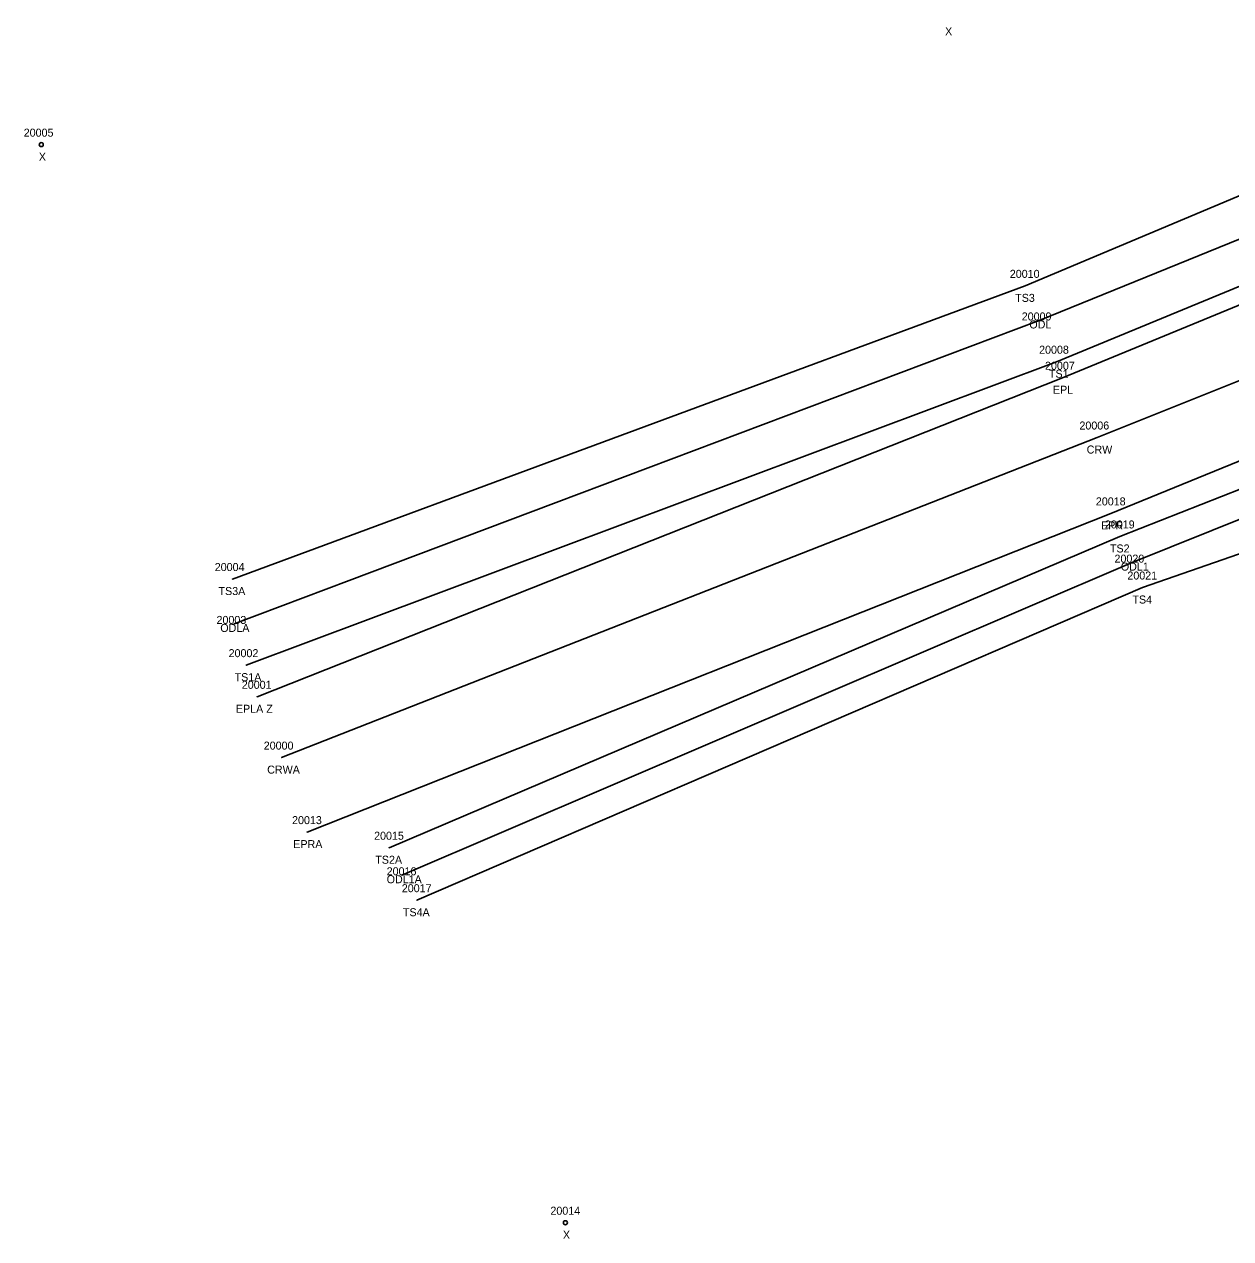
# Model space of a CAD drawing. Extents: x 1966740 to 1969291, y 1117378 to 1118461.
# Drawn here: x 1966740.4 to 1966891.2, y 1117389.8 to 1117541.5 of the extents above; entities that cross this region are included whole.
import ezdxf

# ---------------------------------------------------------------- set-up
doc = ezdxf.new("R2010")
doc.units = 0
for name, color, linetype in [('RD_DTM_BkLn1', 7, 'Continuous'), ('RD_DTM_BkLn2', 7, 'Continuous'), ('RD_EX_H2O', 7, 'Continuous'), ('RD_EX_H2O_txCode', 7, 'Continuous'), ('RD_EX_Road', 7, 'Continuous'), ('RD_EX_Road_txCode', 7, 'Continuous'), ('RD_SMD_Locator', 7, 'Continuous'), ('RD_SMD_Misc', 7, 'Continuous')]:
    doc.layers.add(name, color=color, linetype=linetype)

msp = doc.modelspace()

# ---------------------------------------------------------------- linework, layer by layer
at = {"layer": 'RD_DTM_BkLn1'}
msp.add_lwpolyline([(1966772.57, 1117449.88), (1966874.49, 1117489.87), (1966974.64, 1117529.93), (1967075.06, 1117571.68), (1967175.91, 1117613.34), (1967274.11, 1117653.69), (1967325.25, 1117674.8), (1967374.73, 1117695), (1967473.9, 1117733.1), (1967569.8, 1117771.9), (1967665.19, 1117809.79), (1967697.89, 1117822.8)], dxfattribs=at)
at = {"layer": 'RD_DTM_BkLn2'}
for points in [[(1966768.15, 1117461.43), (1966869.41, 1117499.34), (1967070.52, 1117582.35), (1967171.25, 1117624.02), (1967269.74, 1117664.9), (1967320.21, 1117685.71), (1967369.37, 1117708.48), (1967468.51, 1117746.66), (1967564.6, 1117784.47), (1967654.68, 1117828.05), (1967680.1, 1117841.48), (1967687.91, 1117842.93), (1967691.45, 1117838.71), (1967693.03, 1117834.22)], [(1966766.42, 1117472.19), (1966865.47, 1117508.82), (1967066.64, 1117593.45), (1967166.55, 1117636.11), (1967264.62, 1117677.56), (1967315.66, 1117698.57), (1967367.9, 1117716.34), (1967464.92, 1117753.87), (1967560.73, 1117793.63)], [(1966786.01, 1117438.62), (1966877.32, 1117477.51), (1966981.49, 1117518.47), (1967035.72, 1117540.87), (1967038.77, 1117541.05)], [(1966789.47, 1117432.06), (1966880.12, 1117471.13), (1966985.94, 1117507.88), (1967038.45, 1117537.97), (1967038.77, 1117541.05)]]:
    msp.add_lwpolyline(points, dxfattribs=at)
at = {"layer": 'RD_EX_H2O'}
for points in [[(1966766.64, 1117466.58), (1966867.24, 1117504.5), (1967068.76, 1117586.41), (1967167.95, 1117632.67), (1967266.82, 1117671.88), (1967316.79, 1117693.47), (1967368.01, 1117713.34), (1967465.67, 1117751.74), (1967560.73, 1117793.63)], [(1966787.6, 1117435.18), (1966878.84, 1117474.24), (1966982.42, 1117515.88), (1967036.47, 1117539.68)]]:
    msp.add_lwpolyline(points, dxfattribs=at)
at = {"layer": 'RD_EX_Road'}
for points in [[(1966769.51, 1117457.48), (1966870.16, 1117497.34), (1966971.19, 1117538.95), (1967071.09, 1117580.24), (1967172.6, 1117621.53), (1967270.79, 1117661.66), (1967321.12, 1117682.57), (1967371.52, 1117702.88), (1967470.26, 1117741.55), (1967566.67, 1117779.5), (1967661.25, 1117817.53), (1967694.4, 1117831.19), (1967697.89, 1117822.8)], [(1966775.75, 1117440.57), (1966876.18, 1117480.39), (1966978.46, 1117522.15), (1967078.26, 1117563.06), (1967180.7, 1117605.06), (1967277.98, 1117644.72), (1967308.82, 1117656.67)]]:
    msp.add_lwpolyline(points, dxfattribs=at)
at = {"layer": 'RD_SMD_Locator'}
for centre, radius in [((1966742.55, 1117526.46), 0.25), ((1966865.47, 1117508.82), 0.001), ((1966867.24, 1117504.5), 0.001), ((1966869.41, 1117499.34), 0.001), ((1966870.16, 1117497.34), 0.001), ((1966874.49, 1117489.87), 0.001), ((1966876.18, 1117480.39), 0.001), ((1966877.32, 1117477.51), 0.001), ((1966878.84, 1117474.24), 0.001), ((1966766.42, 1117472.19), 0.001), ((1966880.12, 1117471.13), 0.001), ((1966766.64, 1117466.58), 0.001), ((1966768.15, 1117461.43), 0.001), ((1966769.51, 1117457.48), 0.001), ((1966772.57, 1117449.88), 0.001), ((1966775.75, 1117440.57), 0.001), ((1966786.01, 1117438.62), 0.001), ((1966787.6, 1117435.18), 0.001), ((1966789.47, 1117432.06), 0.001), ((1966808.03, 1117391.77), 0.25)]:
    msp.add_circle(centre, radius, dxfattribs=at)

# ---------------------------------------------------------------- texts
at = {"layer": 'RD_EX_H2O_txCode'}
for s, p in [('20009', (1966865.05, 1117504.5)), ('ODL', (1966866, 1117503.5)), ('20020', (1966876.64, 1117474.24)), ('ODL1', (1966877.43, 1117473.24)), ('20003', (1966764.44, 1117466.58)), ('ODLA', (1966764.91, 1117465.58)), ('ODL1A', (1966785.7, 1117434.18)), ('20016', (1966785.7, 1117435.18))]:
    msp.add_text(s, height=1, dxfattribs=at).set_placement(p)
at = {"layer": 'RD_EX_Road_txCode'}
for s, p in [('20007', (1966867.96, 1117498.34)), ('EPL', (1966868.95, 1117495.34)), ('20018', (1966874.31, 1117481.39)), ('EPR', (1966874.96, 1117478.39)), ('20001', (1966767.6, 1117458.48)), ('EPLA Z', (1966766.86, 1117455.48)), ('20013', (1966773.88, 1117441.57)), ('EPRA', (1966774.03, 1117438.57))]:
    msp.add_text(s, height=1, dxfattribs=at).set_placement(p)
at = {"layer": 'RD_SMD_Misc'}
for s, p in [('X', (1966855.47, 1117540.12)), ('20005', (1966740.35, 1117527.46)), ('X', (1966742.24, 1117524.46)), ('20010', (1966863.56, 1117509.82)), ('TS3', (1966864.23, 1117506.82)), ('20008', (1966867.22, 1117500.34)), ('TS1', (1966868.45, 1117497.34)), ('20006', (1966872.26, 1117490.87)), ('CRW', (1966873.17, 1117487.87)), ('20019', (1966875.44, 1117478.51)), ('TS2', (1966876.07, 1117475.51)), ('20004', (1966764.22, 1117473.19)), ('20021', (1966878.25, 1117472.13)), ('TS3A', (1966764.69, 1117470.19)), ('TS4', (1966878.88, 1117469.13)), ('20002', (1966765.95, 1117462.43)), ('TS1A', (1966766.7, 1117459.43)), ('20000', (1966770.34, 1117450.88)), ('CRWA', (1966770.77, 1117447.88)), ('20015', (1966784.13, 1117439.62)), ('TS2A', (1966784.28, 1117436.62)), ('20017', (1966787.59, 1117433.06)), ('TS4A', (1966787.73, 1117430.06)), ('20014', (1966806.16, 1117392.77)), ('X', (1966807.72, 1117389.77))]:
    msp.add_text(s, height=1, dxfattribs=at).set_placement(p)

doc.saveas('drawing.dxf')
